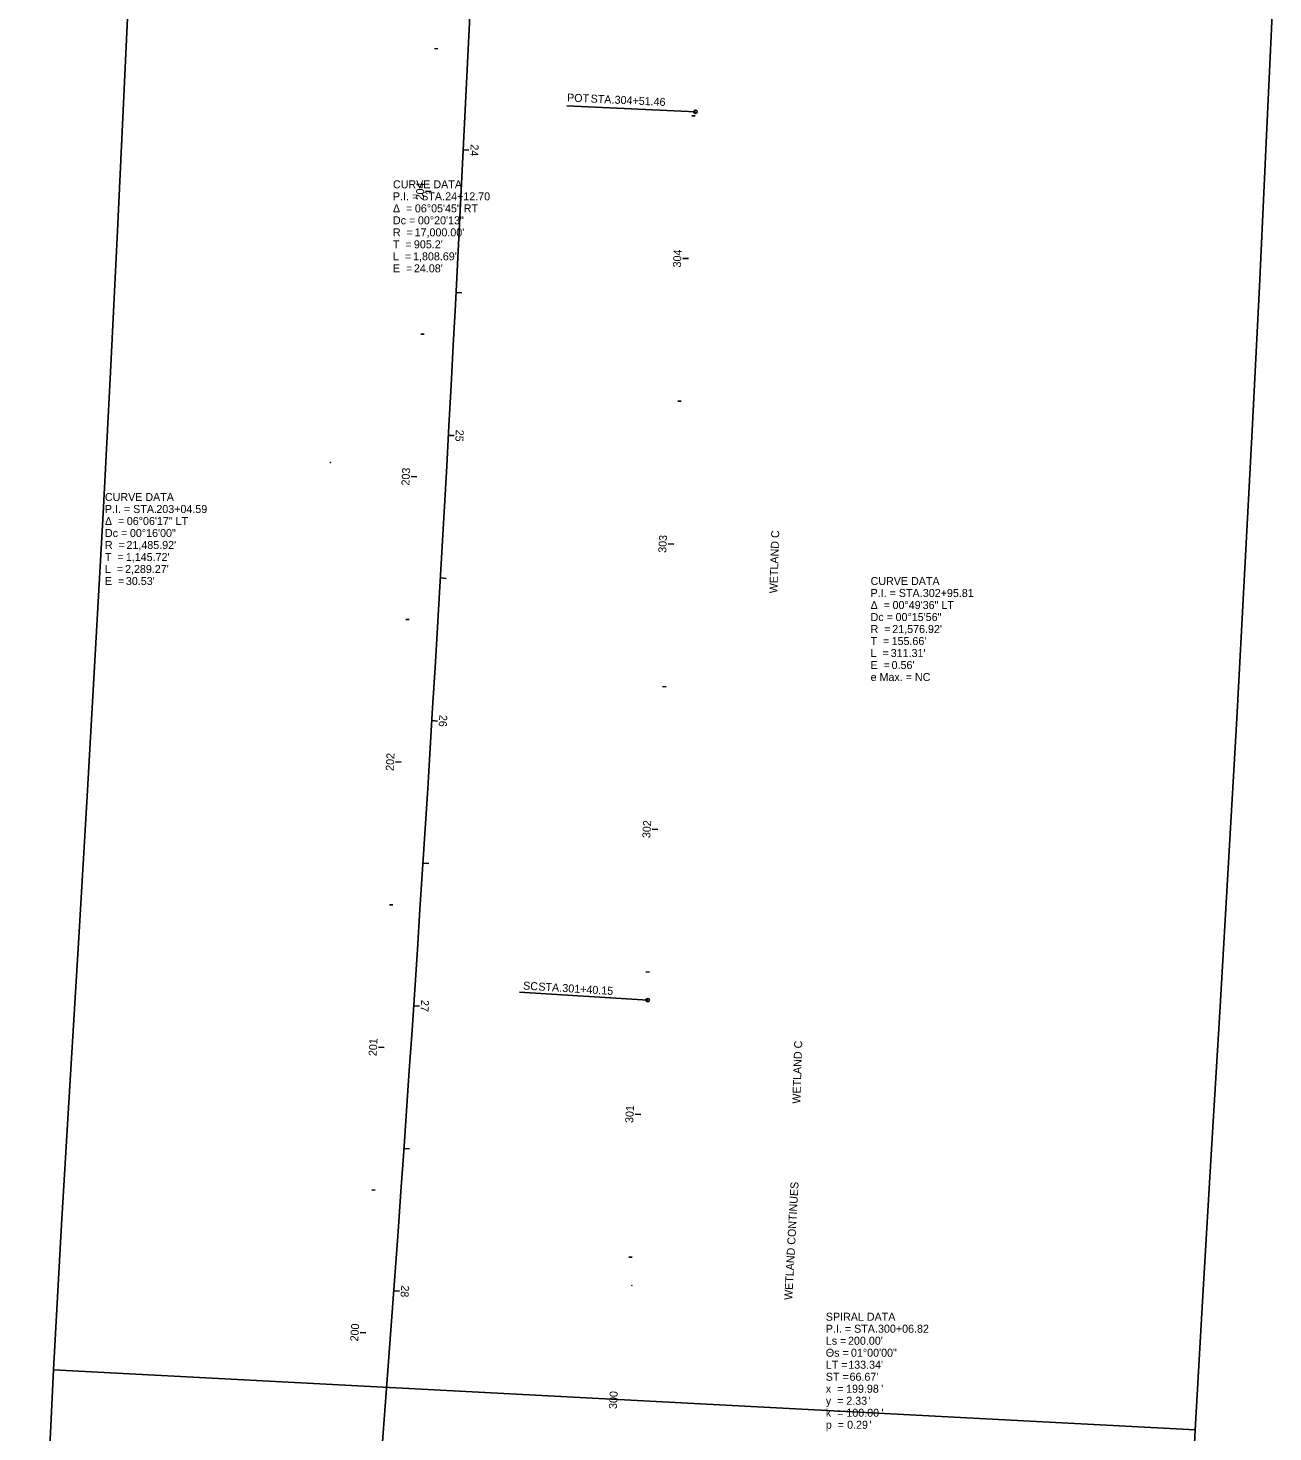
# Model space of a CAD drawing. Extents: x 172043 to 172958, y 249504 to 260295.
# Drawn here: x 172346 to 172781.5, y 256888.2 to 257379.4 of the extents above; entities that cross this region are included whole.
import ezdxf

# ---------------------------------------------------------------- set-up
doc = ezdxf.new("R2010")
doc.units = 0
for name, color, linetype in [('DR_X_Cells', 7, 'Continuous'), ('DR_X_Storm_Sewer', 7, 'Continuous'), ('LT_X_Poles', 7, 'Continuous'), ('PV_X_EOP', 7, 'Continuous'), ('RD_X_Fence', 7, 'Continuous'), ('RW_X_CL_100_Bearings', 7, 'Continuous'), ('RW_X_CL_100_Cardinal_Points', 7, 'Continuous'), ('RW_X_CL_100_Stations', 7, 'Continuous'), ('SC_Scratch1', 7, 'Continuous')]:
    doc.layers.add(name, color=color, linetype=linetype)

msp = doc.modelspace()

# ---------------------------------------------------------------- linework, layer by layer
at = {"layer": 'DR_X_Cells'}
for centre in [(172451.78, 257227.45), (172451.78, 257227.45), (172451.78, 257227.45), (172557.28, 256939.45)]:
    msp.add_circle(centre, 0.05, dxfattribs=at)
at = {"layer": 'DR_X_Storm_Sewer'}
for points in [[(172354.92, 256909.87), (172754.37, 256888.9), (172757.07, 256937.87), (172759.98, 256987.16), (172763.02, 257037.05), (172766.01, 257087.42), (172768.88, 257137.8), (172771.63, 257188.19), (172774.27, 257238.59), (172776.8, 257288.99), (172779.2, 257339.39), (172781.53, 257389.35), (172381.96, 257407.93), (172379.64, 257358), (172377.27, 257308.52), (172374.8, 257259.05), (172372.21, 257209.58), (172369.5, 257160.11), (172366.68, 257110.66), (172363.75, 257061.21), (172360.71, 257011.28), (172357.73, 256960.74)], [(172345.99, 256399.91), (172745.99, 256399.15), (172746.09, 256449.15), (172746.18, 256499.15), (172746.28, 256549.15), (172746.37, 256599.15), (172746.66, 256647.48), (172747.36, 256695.73), (172748.49, 256743.97), (172750.04, 256792.2), (172752.01, 256840.45), (172754.37, 256888.9), (172354.92, 256909.87), (172352.41, 256858.44), (172350.3, 256806.77), (172348.64, 256755.05), (172347.43, 256703.32), (172346.68, 256651.58), (172346.37, 256599.91), (172346.28, 256549.91), (172346.18, 256499.91), (172346.09, 256449.91)]]:
    msp.add_lwpolyline(points, close=True, dxfattribs=at)
at = {"layer": 'PV_X_EOP'}
for p, q in [((172489.41, 257372.17), (172488.21, 257372.23)), ((172487.07, 257322.23), (172485.07, 257322.32)), ((172484.61, 257272.29), (172483.41, 257272.35)), ((172482.04, 257222.35), (172480.04, 257222.46)), ((172479.35, 257172.43), (172478.15, 257172.49)), ((172476.55, 257122.5), (172474.55, 257122.62)), ((172473.63, 257072.59), (172472.43, 257072.66)), ((172470.59, 257022.68), (172468.59, 257022.81)), ((172467.44, 256972.78), (172466.24, 256972.86)), ((172464.17, 256922.89), (172462.17, 256923.02))]:
    msp.add_line(p, q, dxfattribs=at)
at = {"layer": 'RW_X_CL_100_Bearings'}
for p, q in [((172579.49, 257350.16), (172534.54, 257352.25)), ((172562.78, 257039.3), (172517.87, 257042.04))]:
    msp.add_line(p, q, dxfattribs=at)
for centre in [(172579.49, 257350.16), (172562.78, 257039.3)]:
    msp.add_circle(centre, 0.6, dxfattribs=at)
at = {"layer": 'RW_X_CL_100_Stations'}
for p, q in [((172579.42, 257348.7), (172578.22, 257348.75)), ((172577.04, 257298.75), (172575.04, 257298.85)), ((172574.54, 257248.82), (172573.34, 257248.88)), ((172571.92, 257198.88), (172569.92, 257198.99)), ((172569.19, 257148.96), (172567.99, 257149.03)), ((172566.34, 257099.04), (172564.35, 257099.16)), ((172563.38, 257049.13), (172562.18, 257049.2)), ((172560.35, 256999.22), (172558.35, 256999.34)), ((172557.4, 256949.31), (172556.2, 256949.38)), ((172554.65, 256899.38), (172552.66, 256899.49))]:
    msp.add_line(p, q, dxfattribs=at)
at = {"layer": 'SC_Scratch1'}
for p, q in [((172498.25, 257336.78), (172500.25, 257336.68)), ((172498.25, 257336.78), (172500.25, 257336.68)), ((172495.73, 257286.85), (172497.72, 257286.74)), ((172493.05, 257236.92), (172495.05, 257236.81)), ((172493.05, 257236.92), (172495.05, 257236.81)), ((172490.23, 257187), (172492.23, 257186.88)), ((172487.26, 257137.09), (172489.26, 257136.96)), ((172487.26, 257137.09), (172489.26, 257136.96)), ((172484.15, 257087.18), (172486.15, 257087.06)), ((172480.89, 257037.29), (172482.89, 257037.16)), ((172480.89, 257037.29), (172482.89, 257037.16)), ((172477.48, 256987.41), (172479.48, 256987.27)), ((172473.93, 256937.53), (172475.92, 256937.39)), ((172473.93, 256937.53), (172475.92, 256937.39))]:
    msp.add_line(p, q, dxfattribs=at)
msp.add_arc((155518.73, 258170.95), 17000, 354.099581, 0.195474, dxfattribs=at)
msp.add_arc((155518.73, 258170.95), 17000, 354.099581, 0.195474, dxfattribs=at)

# ---------------------------------------------------------------- texts
at = {"layer": 'LT_X_Poles'}
for s, height, rotation, p in [('WETLAND C', 2.8, 88.2384, (172608.14, 257181.61)), ('WETLAND C', 2.8, 88.2384, (172616.18, 257003.01)), ('WETLAND CONTINUES', 2.8003, 86.878, (172613.33, 256934.3))]:
    msp.add_text(s, height=height, rotation=rotation, dxfattribs=at).set_placement(p)
at = {"layer": 'PV_X_EOP'}
for s, rotation, p in [('204', 87.2516, (172484.41, 257319.07)), ('203', 86.9849, (172479.37, 257219.29)), ('202', 86.7182, (172473.87, 257119.44)), ('201', 86.4516, (172467.89, 257019.62)), ('200', 86.1849, (172461.46, 256919.79))]:
    msp.add_text(s, height=2.8, rotation=rotation, dxfattribs=at).set_placement(p)
at = {"layer": 'RD_X_Fence'}
for s, p in [('CURVE DATA', (172372.88, 257213.94)), ('P.I. = STA. ', (172372.88, 257209.74)), ('203+04.59', (172390.87, 257209.74)), ('Δ  = ', (172372.88, 257205.54)), ('06°06\'17" LT', (172380.53, 257205.54)), ('Dc = ', (172372.88, 257201.34)), ('00°16\'00"', (172381.63, 257201.34)), ('R  = ', (172372.88, 257197.14)), ("21,485.92'", (172380.42, 257197.14)), ('T  = ', (172372.88, 257192.94)), ('L  = ', (172372.88, 257188.74)), ("2,289.27'", (172379.92, 257188.74)), ("1,145.72'", (172380.2, 257192.94)), ('E  = ', (172372.88, 257184.54)), ("30.53'", (172380.22, 257184.54))]:
    msp.add_text(s, height=2.8, dxfattribs=at).set_placement(p)
at = {"layer": 'RW_X_CL_100_Bearings'}
for s, rotation, p in [('POT', 357.3374, (172534.52, 257353.76)), (' STA. ', 357.3374, (172541.71, 257353.43)), ('304+51.46', 357.3374, (172551.16, 257352.99)), ('SC', 356.5108, (172519.12, 257043.01)), (' STA. ', 356.5108, (172523.42, 257042.74)), ('301+40.15', 356.5108, (172532.85, 257042.17))]:
    msp.add_text(s, height=2.8, rotation=rotation, dxfattribs=at).set_placement(p)
at = {"layer": 'RW_X_CL_100_Cardinal_Points'}
for s, p in [('CURVE DATA', (172640.77, 257184.54)), ('P.I. = STA. ', (172640.77, 257180.34)), ('302+95.81', (172659.04, 257180.34)), ('Δ  = ', (172640.77, 257176.14)), ('00°49\'36" LT', (172648.45, 257176.14)), ('Dc = ', (172640.77, 257171.94)), ('00°15\'56"', (172649.51, 257171.94)), ('R  = ', (172640.77, 257167.74)), ("21,576.92'", (172648.35, 257167.74)), ('T  = ', (172640.77, 257163.54)), ('L  = ', (172640.77, 257159.34)), ("311.31'", (172647.81, 257159.34)), ("155.66'", (172648.11, 257163.54)), ('E  = ', (172640.77, 257155.14)), ("0.56'", (172648.11, 257155.14)), ('e Max. = NC', (172640.77, 257150.94)), ('SPIRAL DATA', (172625.1, 256927.1)), ('P.I. = STA. ', (172625.1, 256922.9)), ('Ls = ', (172625.1, 256918.7)), ("200.00'", (172632.86, 256918.7)), ('300+06.82', (172643.36, 256922.9)), ('Θs = ', (172625.1, 256914.5)), ('01°00\'00"', (172633.9, 256914.5)), ('LT = ', (172625.1, 256910.3)), ("133.34'", (172632.95, 256910.3)), ('ST = ', (172625.1, 256906.1)), ("66.67'", (172633.4, 256906.1)), ('x  = ', (172625.1, 256901.9)), ('199.98', (172632.19, 256901.9)), ("'", (172644.48, 256901.9)), ('y  = ', (172625.1, 256897.7)), ('2.33', (172632.26, 256897.7)), ("'", (172640.08, 256897.7)), ('k  = ', (172625.1, 256893.5)), ('100.00', (172632.29, 256893.5)), ('0.29', (172632.55, 256889.3)), ("'", (172640.37, 256889.3)), ("'", (172644.58, 256893.5)), ('p  = ', (172625.1, 256889.3))]:
    msp.add_text(s, height=2.8, dxfattribs=at).set_placement(p)
at = {"layer": 'RW_X_CL_100_Stations'}
for s, rotation, p in [('304', 87.2008, (172574.38, 257295.61)), ('303', 86.9352, (172569.25, 257195.75)), ('302', 86.6697, (172563.66, 257095.91)), ('301', 86.5511, (172557.66, 256996.23)), ('300', 87.0018, (172551.98, 256896.17))]:
    msp.add_text(s, height=2.8, rotation=rotation, dxfattribs=at).set_placement(p)
at = {"layer": 'SC_Scratch1'}
for s, rotation, p in [('24', 267.1874, (172500.86, 257338.81)), ('25', 266.8504, (172495.67, 257238.96)), ('26', 266.5134, (172489.9, 257139.17)), ('27', 266.1763, (172483.54, 257039.42)), ('28', 265.8393, (172476.58, 256939.56))]:
    msp.add_text(s, height=2.8, rotation=rotation, dxfattribs=at).set_placement(p)
for s, p in [('CURVE DATA', (172473.65, 257323.35)), ('P.I. = STA. ', (172473.65, 257319.15)), ('24+12.70', (172491.92, 257319.15)), ('Δ  = ', (172473.65, 257314.95)), ('06°05\'45" RT', (172481.33, 257314.95)), ('Dc = ', (172473.65, 257310.75)), ('R  = ', (172473.65, 257306.55)), ("17,000.00'", (172481.23, 257306.55)), ('00°20\'13"', (172482.39, 257310.75)), ('T  = ', (172473.65, 257302.35)), ("905.2'", (172480.99, 257302.35)), ('L  = ', (172473.65, 257298.15)), ("1,808.69'", (172480.69, 257298.15)), ('E  = ', (172473.65, 257293.95)), ("24.08'", (172480.99, 257293.95))]:
    msp.add_text(s, height=2.8, dxfattribs=at).set_placement(p)

doc.saveas('drawing.dxf')
